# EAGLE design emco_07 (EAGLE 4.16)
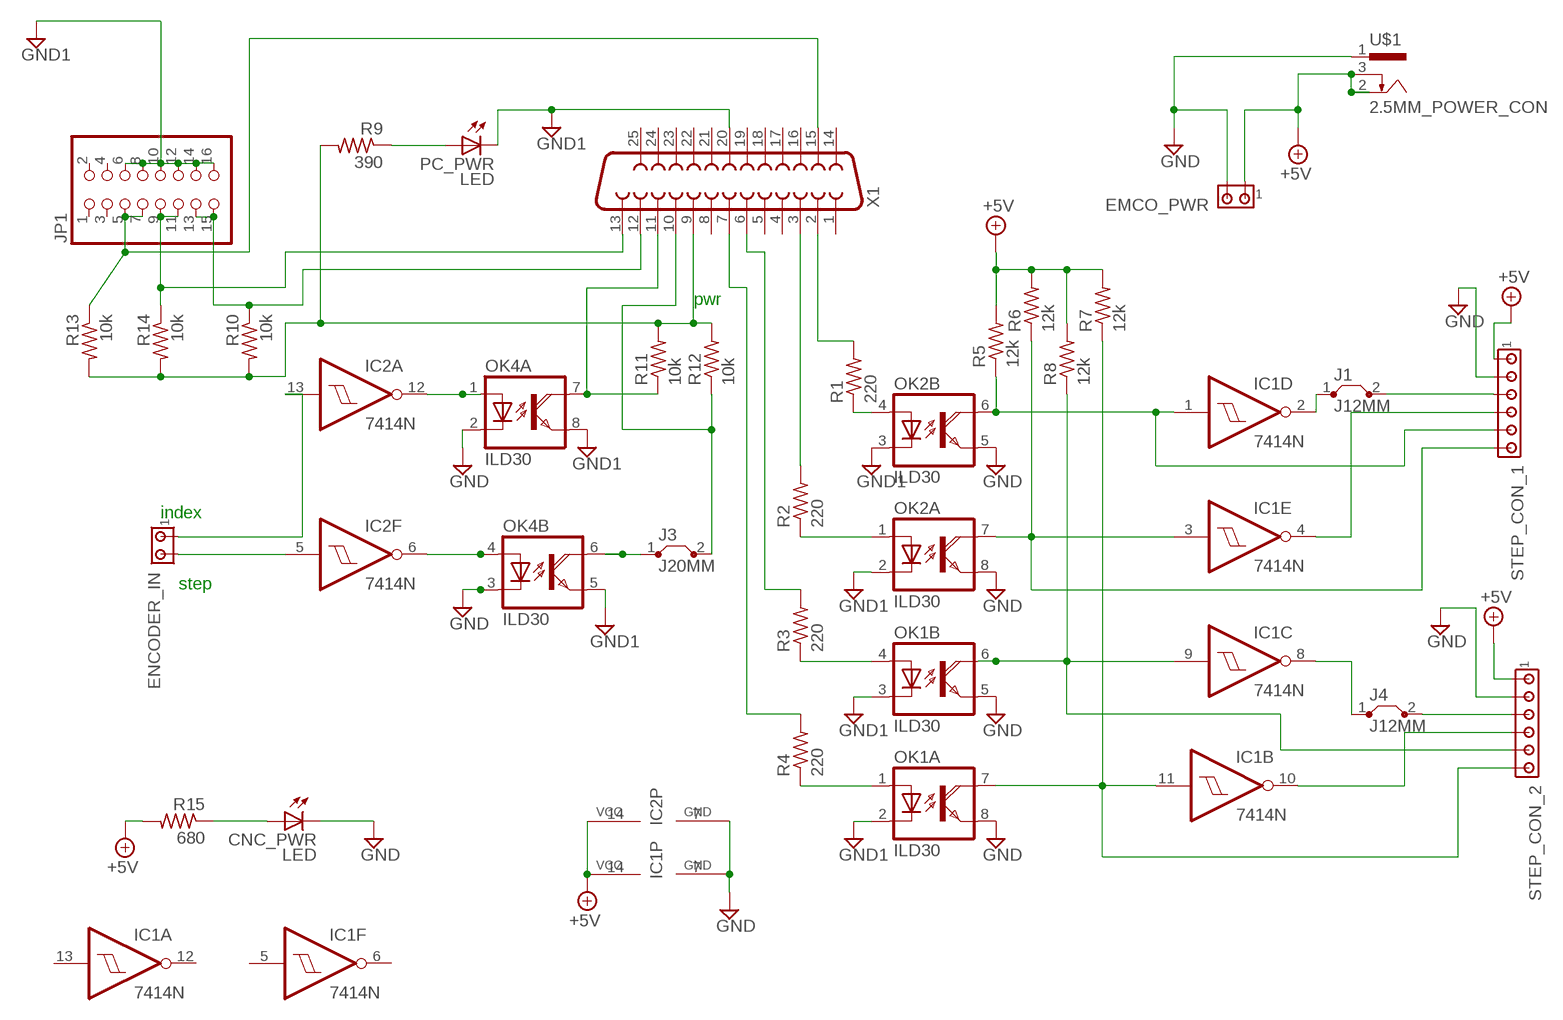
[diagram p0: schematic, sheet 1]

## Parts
CNC_PWR  LED  [LED5MM]
EMCO_PWR  MTA02-100  [10X02MTA]
ENCODER_IN  MTA02-100  [10X02MTA]
IC1  7414N  [DIL14]
IC2  7414N  [DIL14]
J1  J12MM  [12]
J3  J20MM  [20]
J4  J12MM  [12]
JP1  PINHD-2X8  [2X08]
OK1  ILD30  [DIL08]
OK2  ILD30  [DIL08]
OK4  ILD30  [DIL08]
PC_PWR  LED  [LED5MM]
R1  220  R-US_0207/10  [0207/10]
R2  220  R-US_0207/10  [0207/10]
R3  220  R-US_0207/12  [0207/12]
R4  220  R-US_0207/12  [0207/12]
R5  12k  R-US_0207/10  [0207/10]
R6  12k  R-US_0207/10  [0207/10]
R7  12k  R-US_0207/10  [0207/10]
R8  12k  R-US_0207/10  [0207/10]
R9  390  R-US_0207/10  [0207/10]
R10  10k  R-US_0207/10  [0207/10]
R11  10k  R-US_0207/10  [0207/10]
R12  10k  R-US_0207/10  [0207/10]
R13  10k  R-US_0207/10  [0207/10]
R14  10k  R-US_0207/10  [0207/10]
R15  680  R-US_0207/10  [0207/10]
STEP_CON_1  MTA06-100  [10X06MTA]
STEP_CON_2  MTA06-100  [10X06MTA]
U$1  2.5MM_POWER_CON  [2.5MM_POWER_CON]
X1  F25H  [F25H]

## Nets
+5V: EMCO_PWR.1 IC1.14(P:VCC) IC2.14(P:VCC) R5.2 R6.2 R7.2 R8.2 R15.2 STEP_CON_1.1 STEP_CON_2.1 U$1.2 U$1.3
GND: CNC_PWR.K(C) EMCO_PWR.2 IC1.7(P:GND) IC2.7(P:GND) OK1.5(B:EMI) OK1.8(A:EMI) OK2.5(B:EMI) OK2.8(A:EMI) OK4.2(A:C) OK4.3(B:C) STEP_CON_1.2 STEP_CON_2.2 U$1.1
GND1: JP1.6 JP1.8 JP1.10 JP1.12 JP1.14 JP1.16 OK1.2(A:C) OK1.3(B:C) OK2.2(A:C) OK2.3(B:C) OK4.5(B:EMI) OK4.8(A:EMI) PC_PWR.K(C) X1.20
N$1: IC1.1(D:I) OK2.6(B:COL) R5.1 STEP_CON_1.5
N$2: IC1.3(E:I) OK2.7(A:COL) R6.1 STEP_CON_1.6
N$3: IC1.9(C:I) OK1.6(B:COL) R8.1 STEP_CON_2.5
N$4: IC2.6(F:O) OK4.4(B:A)
N$5: IC1.2(D:O) J1.1
N$6: IC1.4(E:O) STEP_CON_1.4
N$7: IC1.8(C:O) J4.1
N$8: J1.2 STEP_CON_1.3
N$9: OK2.4(B:A) R1.1
N$10: R1.2 X1.2
N$11: R2.2 X1.3
N$12: OK2.1(A:A) R2.1
N$13: R3.2 X1.6
N$14: OK1.4(B:A) R3.1
N$15: OK1.1(A:A) R4.1
N$16: R4.2 X1.7
N$17: IC1.11(B:I) OK1.7(A:COL) R7.1 STEP_CON_2.6
N$18: PC_PWR.A R9.1
N$19: JP1.5 JP1.7 R13.1 X1.15
N$20: J3.1 OK4.6(B:COL)
N$21: OK4.7(A:COL) R11.1 X1.11
N$22: J3.2 R12.1 X1.10
N$23: ENCODER_IN.2 IC2.5(F:I)
N$24: JP1.13 JP1.15 R10.1 X1.12
N$25: J4.2 STEP_CON_2.3
N$26: ENCODER_IN.1 IC2.13(A:I)
N$28: JP1.9 JP1.11 R14.1 X1.13
N$30: R9.2 R10.2 R11.2 R12.2 R13.2 R14.2 X1.9
N$31: IC1.10(B:O) STEP_CON_2.4
N$32: IC2.12(A:O) OK4.1(A:A)
N$35: CNC_PWR.A R15.1
Unconnected: IC1.5(F:I) IC1.6(F:O) IC1.12(A:O) IC1.13(A:I) IC2.1(D:I) IC2.2(D:O) IC2.3(E:I) IC2.4(E:O) IC2.8(C:O) IC2.9(C:I) IC2.10(B:O) IC2.11(B:I) JP1.1 JP1.2 JP1.3 JP1.4 X1.1 X1.4 X1.5 X1.8 X1.14 X1.16 X1.17 X1.18 X1.19 X1.21 X1.22 X1.23 X1.24 X1.25

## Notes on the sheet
- pwr
- index
- step

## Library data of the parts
CNC_PWR PC_PWR = 1dmf:LED
EMCO_PWR ENCODER_IN = con-amp:MTA02-100: AMP connector
IC1 IC2 = 74xx-us:74*14: Hex schmitt trigger INVERTER
J1 J3 J4 = jumper:J: Bridge
JP1 = pinhead:PINHD-2X8: PIN HEADER
OK1 OK2 OK4 = optocoupler:ILD30: SIEMENS OPTO COUPLER
R1-R15 = rcl:R-US_: RESISTOR, American symbol
STEP_CON_1 STEP_CON_2 = con-amp:MTA06-100: AMP connector
U$1 = 1dmf:2.5MM_POWER_CON
X1 = con-subd:F25: SUB-D

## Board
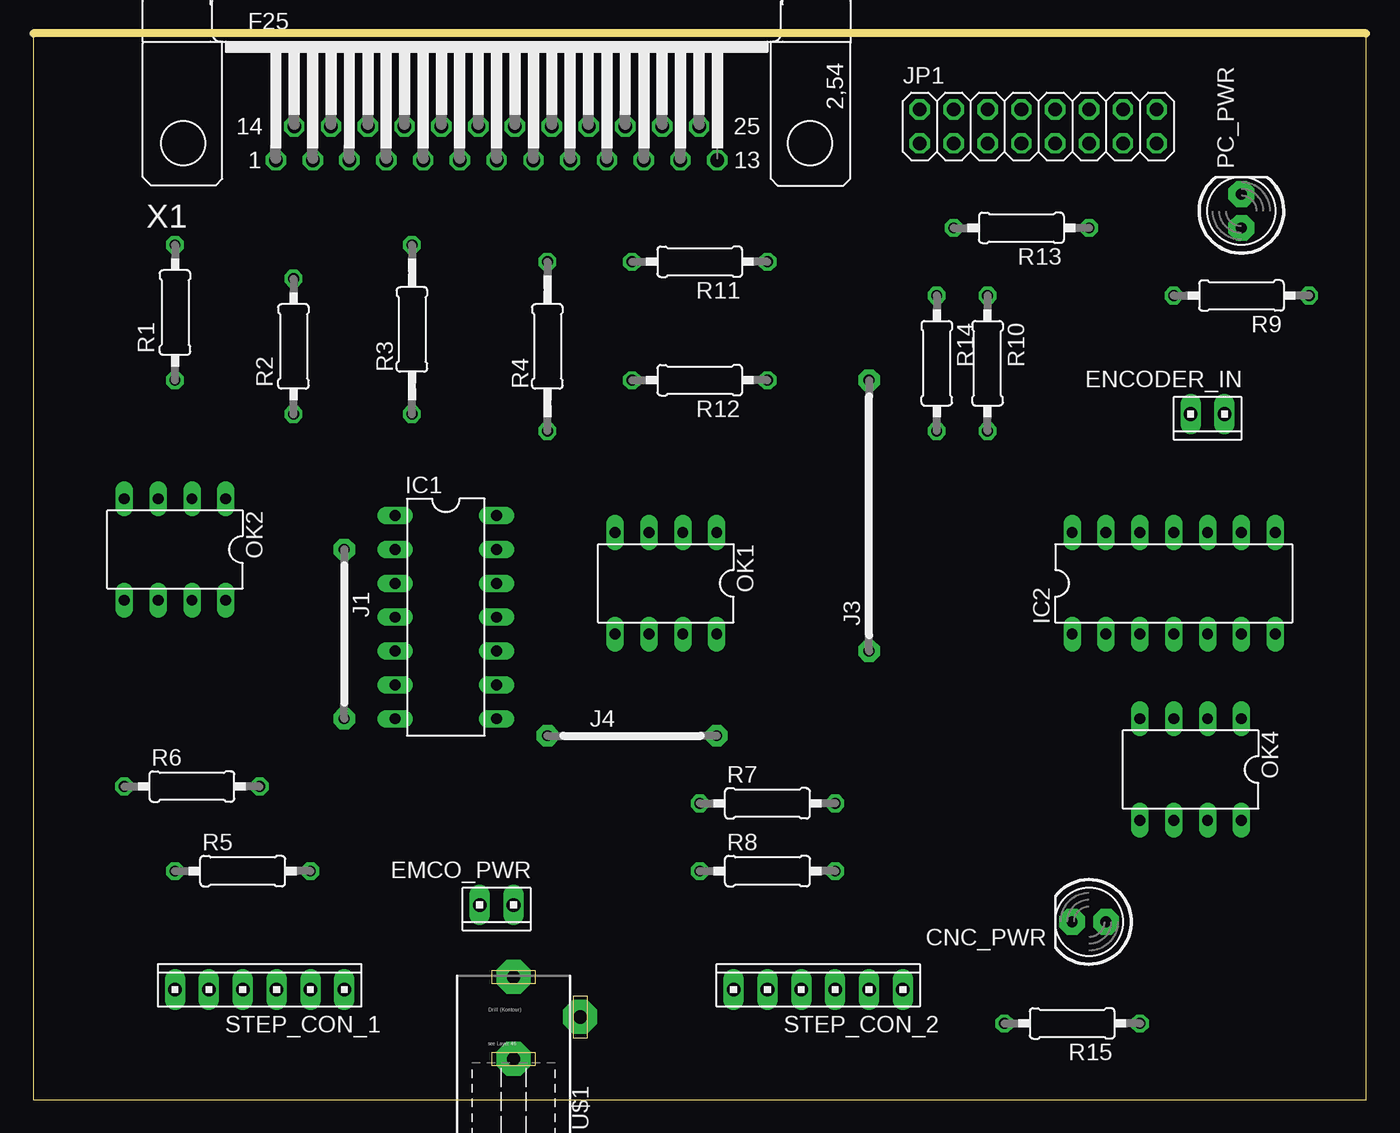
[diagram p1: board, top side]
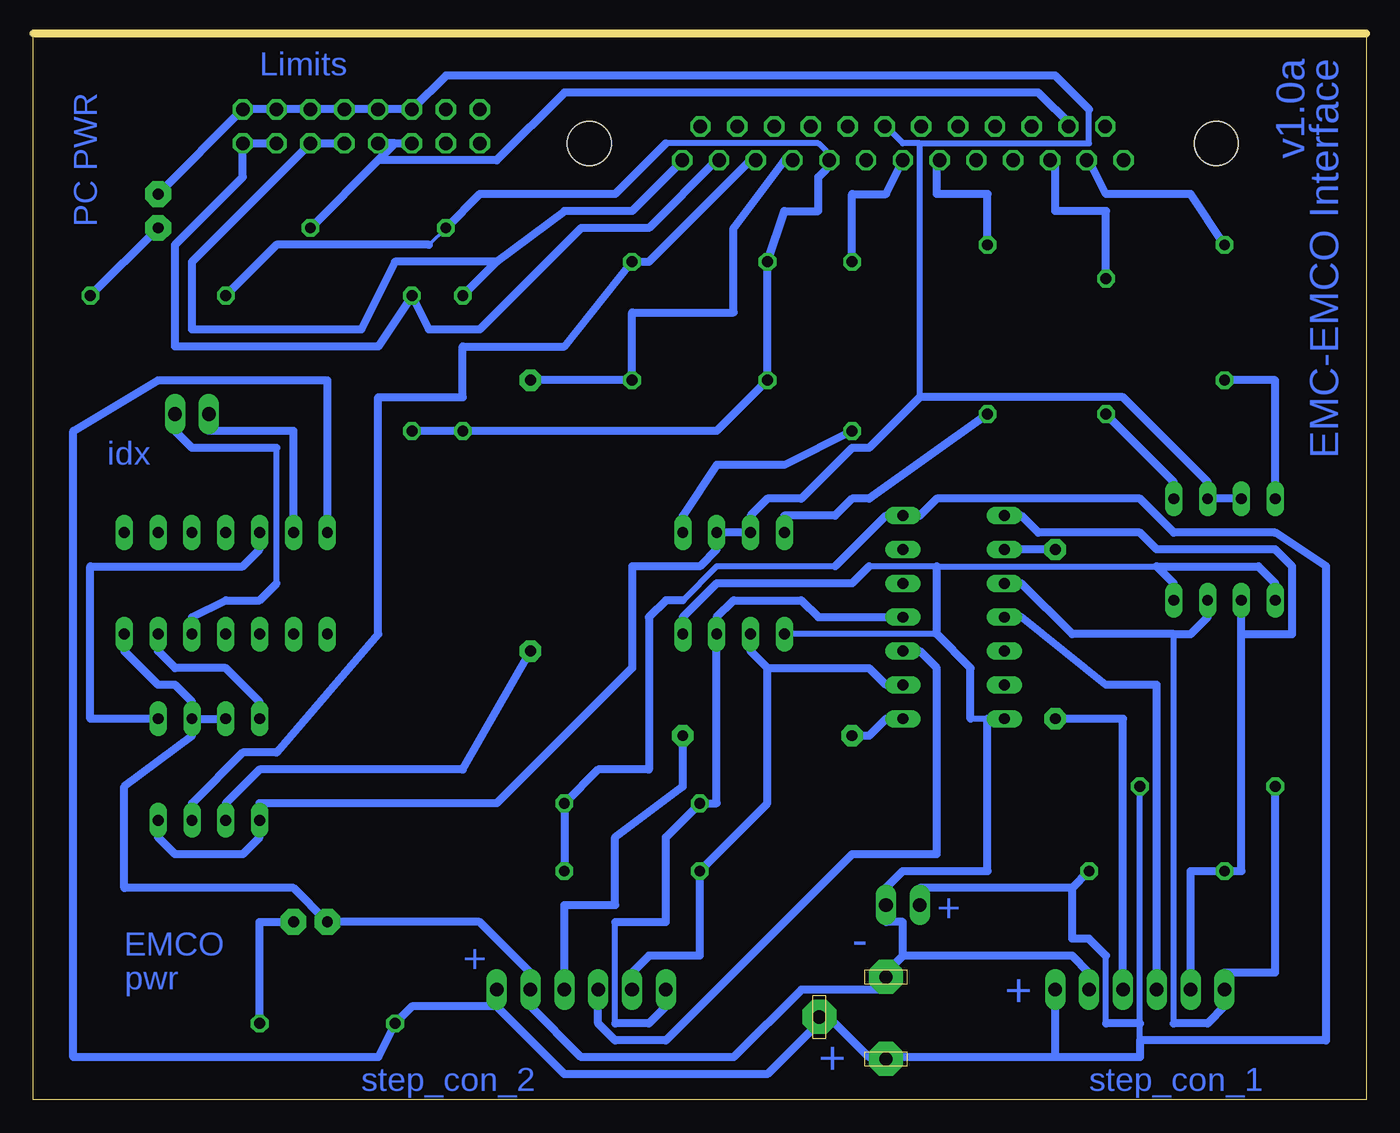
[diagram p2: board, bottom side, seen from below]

Size 100 x 80 mm. Coordinates in mm from the lower left corner, seen from the top.
Outline: 0,0 100,0 100,80 0,80 0,0
Copper layers (1*16): Top 0.035mm / dielectric 1.5mm / Bottom 0.035mm
Design rules "default": minimum track width 10mil, minimum drill 24mil, track to track 8mil, track to pad 8mil, pad to pad 8mil, via to via 8mil, smd to smd 8mil, copper to edge 40mil, drill to drill 8mil, minimum pad ring 10mil, minimum via ring 8mil, stop-mask expansion 4mil, vias tented up to drill 0mil, thermal gap 10mil

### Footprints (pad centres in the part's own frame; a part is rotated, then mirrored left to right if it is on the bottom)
LED5MM = drill 0.813 pad 1.93 octagon: A -1.27,0; K 1.27,0
10X02MTA = drill 1.016 long: 1 1.27,0; 2 -1.27,0
DIL14 = drill 0.813 long: 1 -7.62,-3.81; 2 -5.08,-3.81; 3 -2.54,-3.81; 4 0,-3.81; 5 2.54,-3.81; 6 5.08,-3.81; 7 7.62,-3.81; 8 7.62,3.81; 9 5.08,3.81; 10 2.54,3.81; 11 0,3.81; 12 -2.54,3.81; 13 -5.08,3.81; 14 -7.62,3.81
12 = drill 0.813 pad 1.6 octagon: 1 -6.35,0; 2 6.35,0
20 = drill 0.813 pad 1.6 octagon: 1 -10.16,0; 2 10.16,0
2X08 = drill 1.016 octagon: 1 -8.89,-1.27; 2 -8.89,1.27; 3 -6.35,-1.27; 4 -6.35,1.27; 5 -3.81,-1.27; 6 -3.81,1.27; 7 -1.27,-1.27; 8 -1.27,1.27; 9 1.27,-1.27; 10 1.27,1.27; 11 3.81,-1.27; 12 3.81,1.27; 13 6.35,-1.27; 14 6.35,1.27; 15 8.89,-1.27; 16 8.89,1.27
DIL08 = drill 0.813 long: 1 -3.81,-3.81; 2 -1.27,-3.81; 3 1.27,-3.81; 4 3.81,-3.81; 5 3.81,3.81; 6 1.27,3.81; 7 -1.27,3.81; 8 -3.81,3.81
0207/10 = drill 0.813 octagon: 1 -5.08,0; 2 5.08,0
0207/12 = drill 0.813 octagon: 1 -6.35,0; 2 6.35,0
10X06MTA = drill 1.016 long: 1 6.35,0; 2 3.81,0; 3 1.27,0; 4 -1.27,0; 5 -3.81,0; 6 -6.35,0
2.5MM_POWER_CON = drill 1 pad 2.54 octagon: 1 0,6.03; 2 0,-0.12; 3 5,3.03
F25H = drill 1.016 octagon: 1 -16.561,-1.27; 2 -13.792,-1.27; 3 -11.049,-1.27; 4 -8.28,-1.27; 5 -5.512,-1.27; 6 -2.769,-1.27; 7 0,-1.27; 8 2.769,-1.27; 9 5.512,-1.27; 10 8.28,-1.27; 11 11.049,-1.27; 12 13.792,-1.27; 13 16.561,-1.27; 14 -15.189,1.27; 15 -12.421,1.27; 16 -9.652,1.27; 17 -6.909,1.27; 18 -4.14,1.27; 19 -1.372,1.27; 20 1.372,1.27; 21 4.14,1.27; 22 6.909,1.27; 23 9.652,1.27; 24 12.421,1.27; 25 15.189,1.27 | hole 3.302: -23.52,0; 23.52,0

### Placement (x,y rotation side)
CNC_PWR  79.21,13.33 180 top
EMCO_PWR  34.76,14.6 180 top
ENCODER_IN  88.1,51.43 180 top
IC1  30.95,36.19 270 top
IC2  85.56,38.73 0 top
J1  23.33,34.92 270 top
J3  62.7,43.81 90 top
J4  44.92,27.3 0 top
JP1  75.4,73.02 0 top
OK1  47.46,38.73 180 top
OK2  10.63,41.27 180 top
OK4  86.83,24.76 180 top
PC_PWR  90.64,66.67 90 top
R1  10.63,59.05 90 top
R2  19.52,56.51 90 top
R3  28.41,57.78 90 top
R4  38.57,56.51 90 top
R5  15.71,17.14 0 top
R6  11.9,23.49 0 top
R7  55.08,22.22 0 top
R8  55.08,17.14 0 top
R9  90.64,60.32 180 top
R10  71.59,55.24 270 top
R11  50,62.86 180 top
R12  50,53.97 180 top
R13  74.13,65.4 180 top
R14  67.78,55.24 270 top
R15  77.94,5.71 180 top
STEP_CON_1  16.98,8.25 0 top
STEP_CON_2  58.89,8.25 0 top
U$1  36.03,3.17 0 top
X1  34.76,71.75 0 top

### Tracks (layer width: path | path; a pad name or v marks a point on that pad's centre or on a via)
+5V
  Bottom 0.254: IC1.14 36.03,43.81 | 37.3,3.17 36.03,3.17 U$1.2 | U$1.3 41.11,5.71
  Bottom 0.457: 39.84,40 48.73,40 51.27,37.46 | 16.98,4.44 16.98,5.71 R6.2 | 19.52,5.71 19.52,10.79
  Bottom 0.61: R8.2 R7.2 57.62,24.76 53.81,24.76 53.81,36.19 52.54,37.46 51.27,37.46 | 36.03,43.81 39.84,40 | 22.06,15.87 R5.2 | 22.06,15.87 33.49,15.87 EMCO_PWR.1 | 23.33,3.17 36.03,3.17 | 23.33,3.17 16.98,3.17 16.98,4.44 3.01,4.44 3.01,40 6.82,42.54 14.44,42.54 16.98,45.08 32.22,45.08 33.49,43.81 IC1.14 | 23.33,3.17 STEP_CON_1.1 | 37.3,3.17 39.84,5.71 U$1.3 | 22.06,15.87 22.06,12.06 20.79,12.06 19.52,10.79 | 16.98,5.71 19.52,5.71 | 65.24,6.98 71.59,6.98 R15.2 74.13,3.17 96.99,3.17 96.99,50.16 90.64,53.97 77.94,53.97 IC2.14 | 41.11,5.71 44.92,1.9 60.16,1.9 65.24,6.98 | 65.24,6.98 STEP_CON_2.1
GND
  Bottom 0.254: 93.18,33.65 IC2.7 | 88.1,29.84 OK4.2 88.1,27.3 | STEP_CON_2.2 62.7,9.52 | 51.27,36.19 OK1.8 | 14.44,38.73 OK2.8 | 36.03,9.52 U$1.1 | EMCO_PWR.2 36.03,15.87
  Bottom 0.457: 15.71,40 32.22,40 37.3,40 | 32.22,34.92 OK1.5 | 28.41,28.57 29.68,28.57
  Bottom 0.61: OK4.2 OK4.3 | 93.18,33.65 90.64,31.11 89.37,31.11 88.1,29.84 | 62.7,9.52 66.51,13.33 CNC_PWR.K 80.48,15.87 93.18,15.87 93.18,23.49 88.1,27.3 | 51.27,36.19 48.73,38.73 38.57,38.73 37.3,40 | 14.44,38.73 15.71,40 8.09,40 6.82,38.73 OK2.5 | 34.76,10.79 22.06,10.79 20.79,9.52 STEP_CON_1.2 | 34.76,10.79 36.03,9.52 | 36.03,15.87 34.76,17.14 28.41,17.14 28.41,28.57 IC1.7 | 29.68,28.57 29.68,32.38 32.22,34.92 32.22,40 | 34.76,10.79 34.76,13.33 36.03,13.33 EMCO_PWR.2 | STEP_CON_2.2 62.7,6.98 58.89,3.17 47.46,3.17 42.38,8.25 36.03,8.25 U$1.1
GND1
  Bottom 0.254: OK4.5 83.02,19.68 | 36.03,73.02 X1.20 | OK2.2 11.9,46.35 | 46.19,43.81 OK1.3 | OK1.2 48.73,41.27
  Bottom 0.457: 36.03,73.02 34.76,71.75 33.49,71.75 | 33.49,52.7 33.49,71.75 | 20.79,74.29 20.79,71.75 33.49,71.75
  Bottom 0.61: PC_PWR.K JP1.16 JP1.14 JP1.12 JP1.10 JP1.8 JP1.6 69.05,76.83 23.33,76.83 20.79,74.29 | 83.02,19.68 84.29,18.41 89.37,18.41 90.64,19.68 OK4.8 | OK1.3 OK1.2 | OK2.3 OK2.2 | 11.9,46.35 18.25,52.7 33.49,52.7 37.3,48.89 38.57,48.89 42.38,45.08 44.92,45.08 46.19,43.81 | 48.73,41.27 50,40 55.08,40 55.08,32.38 65.24,22.22 83.02,22.22 OK4.5
N$1
  Bottom 0.61: 9.36,34.92 9.36,17.14 R5.1 13.17,17.14 STEP_CON_1.5 | 9.36,34.92 OK2.6 | 9.36,34.92 5.55,34.92 5.55,40 6.82,41.27 15.71,41.27 16.98,42.54 24.6,42.54 25.87,43.81 IC1.1
N$2
  Bottom 0.254: 11.9,36.19 OK2.7 | 10.63,9.52 STEP_CON_1.6
  Bottom 0.457: 14.44,5.71 14.44,34.92
  Bottom 0.61: 11.9,36.19 13.17,34.92 14.44,34.92 22.06,34.92 25.87,38.73 IC1.3 | R6.1 6.82,9.52 10.63,9.52 | 14.44,5.71 11.9,5.71 10.63,6.98 STEP_CON_1.6
N$3
  Bottom 0.61: STEP_CON_2.5 55.08,9.52 53.81,10.79 50,10.79 R8.1 44.92,22.22 44.92,32.38 | 44.92,32.38 37.3,32.38 36.03,31.11 IC1.9 | 44.92,32.38 46.19,33.65 OK1.6
N$4
  Bottom 0.254: 90.64,33.65 IC2.6
  Bottom 0.61: 90.64,33.65 89.37,32.38 85.56,32.38 83.02,29.84 OK4.4
N$5
  Bottom 0.61: J1.1 IC1.2
N$6
  Bottom 0.61: IC1.4 25.87,36.19 19.52,31.11 15.71,31.11 STEP_CON_1.4
N$7
  Bottom 0.61: J4.1 37.3,27.3 36.03,28.57 IC1.8
N$8
  Bottom 0.61: J1.2 18.25,28.57 STEP_CON_1.3
N$9
  Bottom 0.61: R1.1 6.82,53.97 OK2.4
N$10
  Bottom 0.254: 20.79,70.48 X1.2
  Bottom 0.61: R1.2 13.17,67.94 19.52,67.94 20.79,70.48
N$11
  Bottom 0.254: 23.33,70.48 X1.3
  Bottom 0.61: R2.2 19.52,66.67 23.33,66.67 23.33,70.48
N$12
  Bottom 0.254: OK2.1 14.44,46.35
  Bottom 0.61: 14.44,46.35 R2.1
N$13
  Bottom 0.254: 32.22,70.48 X1.6
  Bottom 0.61: R3.2 28.41,67.94 32.22,67.94 32.22,70.48
N$14
  Bottom 0.61: R3.1 37.3,45.08 38.57,45.08 39.84,43.81 43.65,43.81 OK1.4
N$15
  Bottom 0.61: R4.1 43.65,47.62 48.73,47.62 51.27,43.81 OK1.1
N$16
  Bottom 0.61: R4.2 38.57,67.94 36.03,67.94 X1.7
N$17
  Bottom 0.254: OK1.7 48.73,36.19
  Bottom 0.457: 56.35,5.71 56.35,13.33
  Bottom 0.61: OK1.7 48.73,22.22 R7.1 52.54,19.68 52.54,13.33 56.35,13.33 | 48.73,36.19 47.46,37.46 42.38,37.46 41.11,36.19 IC1.11 | 56.35,5.71 53.81,5.71 52.54,6.98 STEP_CON_2.6
N$18
  Bottom 0.61: R9.1 PC_PWR.A
N$19
  Bottom 0.254: X1.15 22.06,73.02
  Bottom 0.61: 74.13,70.48 72.86,71.75 | 74.13,70.48 R13.1 | 72.86,71.75 JP1.5 | 72.86,71.75 JP1.7 | 22.06,73.02 24.6,75.56 60.16,75.56 65.24,70.48 74.13,70.48
N$20
  Bottom 0.61: J3.1 67.78,24.76 83.02,24.76 85.56,22.22 OK4.6
N$21
  Bottom 0.61: OK4.7 88.1,22.22 84.29,26.03 81.75,26.03 74.13,34.92 74.13,52.7 67.78,52.7 67.78,56.51 60.16,56.51 R11.1 53.81,62.86 46.19,70.48 X1.11
N$22
  Bottom 0.61: J3.2 R12.1 55.08,59.05 47.46,59.05 47.46,65.4 43.65,70.48 X1.10
N$23
  Bottom 0.254: IC2.5 88.1,36.19
  Bottom 0.457: 81.75,38.73 81.75,48.89
  Bottom 0.61: 88.1,36.19 85.56,37.46 83.02,37.46 81.75,38.73 | 81.75,48.89 88.1,48.89 89.37,50.16 ENCODER_IN.2
N$24
  Bottom 0.254: X1.12 48.73,70.48
  Bottom 0.61: JP1.13 JP1.15 84.29,69.21 89.37,64.13 89.37,56.51 74.13,56.51 R10.1 70.32,57.78 66.51,57.78 58.89,65.4 53.81,65.4 48.73,70.48
N$25
  Bottom 0.61: J4.2 51.27,23.49 56.35,19.68 56.35,14.6 60.16,14.6 STEP_CON_2.3
N$26
  Bottom 0.61: IC2.13 80.48,50.16 86.83,50.16 ENCODER_IN.1
N$28
  Bottom 0.254: X1.13 51.27,70.48
  Bottom 0.61: JP1.9 JP1.11 88.1,62.86 88.1,57.78 75.4,57.78 72.86,62.86 65.24,62.86 | 65.24,62.86 60.16,66.67 55.08,66.67 51.27,70.48 | 65.24,62.86 R14.1
N$30
  Bottom 0.254: R13.2 70.32,64.13 | 39.84,70.48 X1.9
  Bottom 0.457: 52.54,71.75 41.11,71.75 39.84,70.48
  Bottom 0.61: R9.2 81.75,64.13 70.32,64.13 | R10.2 R14.2 48.73,50.16 R12.2 R11.2 43.65,66.67 41.11,66.67 41.11,69.21 39.84,70.48 | R13.2 66.51,67.94 56.35,67.94 52.54,71.75
N$31
  Bottom 0.61: IC1.10 33.49,33.65 32.22,32.38 32.22,18.41 38.57,18.41 52.54,4.44 56.35,4.44 57.62,5.71 STEP_CON_2.4
N$32
  Bottom 0.61: OK4.1 95.72,28.57 95.72,40 84.29,40 83.02,41.27 IC2.12
N$35
  Bottom 0.61: R15.1 83.02,13.33 CNC_PWR.A

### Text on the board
Bottom: EMC-EMCO Interface | v1.0a | Limits | PC PWR | idx | + | - | EMCO | + | pwr | + | + | step_con_1 | step_con_2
